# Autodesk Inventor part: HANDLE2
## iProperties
Author: GJOHNST2
Shininess: 20.0
Length Units: 11272
Angle Units: 11286
Time Units: 11279
Mass Units: 11290
Length Display Precision: 3
Angle Display Precision: 2
Compacted: True
PropertySet Name: _Private Model Information
Created: 2001-11
Part Number: HANDLE2
Document SubType Name: Modeling
Designer: GJOHNST2
Control State: 0
Master: False
Checked Out: False
PropertySet Name: Design Tracking Control
Density: 0.0
Volumn: 0.0
Area: 0.0
PropertySet Name: Model Information
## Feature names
1. Derived Body1 [Tagging]
